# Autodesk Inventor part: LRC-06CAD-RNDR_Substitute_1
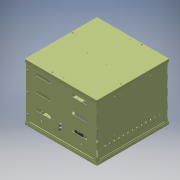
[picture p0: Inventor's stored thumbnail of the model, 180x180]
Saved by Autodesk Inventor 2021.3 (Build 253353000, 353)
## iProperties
Part Number: LRC-06CAD-RNDR_Substitute_1
Material: Generic
Document SubType Name: Modeling
Designer: JChurch
Manufacturer: Standard
Standards Organization: Custom
Density: 1 g/cm^3
Appearance: Smooth - Black
Author: JChurch
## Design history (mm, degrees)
derived "LRC-06CAD-RNDR.iam"
body "Solid9"
node "830399-00-00.ipt:1"
node "881035-00-00.iam:1::830505-04-00.ipt:1"
body "Solid10"
node "881035-00-00.iam:1::850014-00-00.iam:1::805044-00-00.ipt:1"
body "Solid11"
node "881035-00-00.iam:1::850014-00-00.iam:1::805174-00-00.ipt:1"
body "Solid12"
node "881035-00-00.iam:1::850014-00-00.iam:1::502055-00-00.ipt:1"
body "Solid13"
node "881035-00-00.iam:1::850014-00-00.iam:1::502055-00-00.ipt:2"
body "Solid14"
node "881035-00-00.iam:1::850014-00-00.iam:1::507032-00-00.ipt:1"
body "Solid15"
node "881035-00-00.iam:1::502099-00-00.ipt:1"
body "Solid16"
node "881035-00-00.iam:1::502099-00-00.ipt:2"
body "Solid17"
node "881035-00-00.iam:1::502099-00-00.ipt:3"
body "Solid18"
node "881035-00-00.iam:1::500027-00-00.ipt:1"
body "Solid19"
node "881035-00-00.iam:1::500027-00-00.ipt:2"
body "Solid20"
node "881035-00-00.iam:1::501030-00-00.ipt:1"
body "Solid21"
node "881035-00-00.iam:1::501030-00-00.ipt:2"
body "Solid22"
node "881035-00-00.iam:1::501030-00-00.ipt:3"
body "Solid23"
node "881035-00-00.iam:1::501030-00-00.ipt:4"
body "Solid24"
node "881035-00-00.iam:1::501030-00-00.ipt:5"
body "Solid25"
node "881035-00-00.iam:1::501030-00-00.ipt:6"
body "Solid26"
node "881035-00-00.iam:1::500027-00-00.ipt:3"
body "Solid27"
node "881035-00-00.iam:1::500027-00-00.ipt:4"
body "Solid28"
node "881035-00-00.iam:1::501030-00-00.ipt:7"
body "Solid29"
node "881035-00-00.iam:1::501030-00-00.ipt:8"
body "Solid30"
node "830402-00-00.ipt:1"
body "Solid31"
node "725075-00-00.ipt:1"
body "Solid32"
node "750300-01-XX.iam:1::700458-00-XX.iam:1::710139-00-00.ipt:1"
body "Solid33"
node "750300-01-XX.iam:1::700458-00-XX.iam:1::700452-01-00.ipt:1"
body "Solid34"
node "750300-01-XX.iam:1::700458-00-XX.iam:1::510048-00-00_5.72 DI"
body "Solid35"
node "750300-01-XX.iam:1::502040-00-00.ipt:1"
body "Solid36"
node "750300-01-XX.iam:1::507075-00-38.ipt:1"
body "Solid37"
node "750300-01-XX.iam:1::507075-00-38.ipt:2"
body "Solid38"
node "750300-01-XX.iam:1::507014-00-00.ipt:2"
body "Solid39"
node "750300-01-XX.iam:1::805565-00-00.ipt:1"
body "Solid40"
other parameters: "d15" = 61.595, "d16" = 9.525, "d17" = 9.525, "d35" = 5.08
